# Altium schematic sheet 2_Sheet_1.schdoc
size 497 x 243 mm; Name: A_A4; Symbol: A_A4; Device: A_A4; @Project Name: RM_超级电容控制板; REV: 3.4; Date: 2023-02-08; Sheet: 1/3; Draw By: PKKKK; Company: QiDian; Convert to PCB: yes; Add into BOM: yes
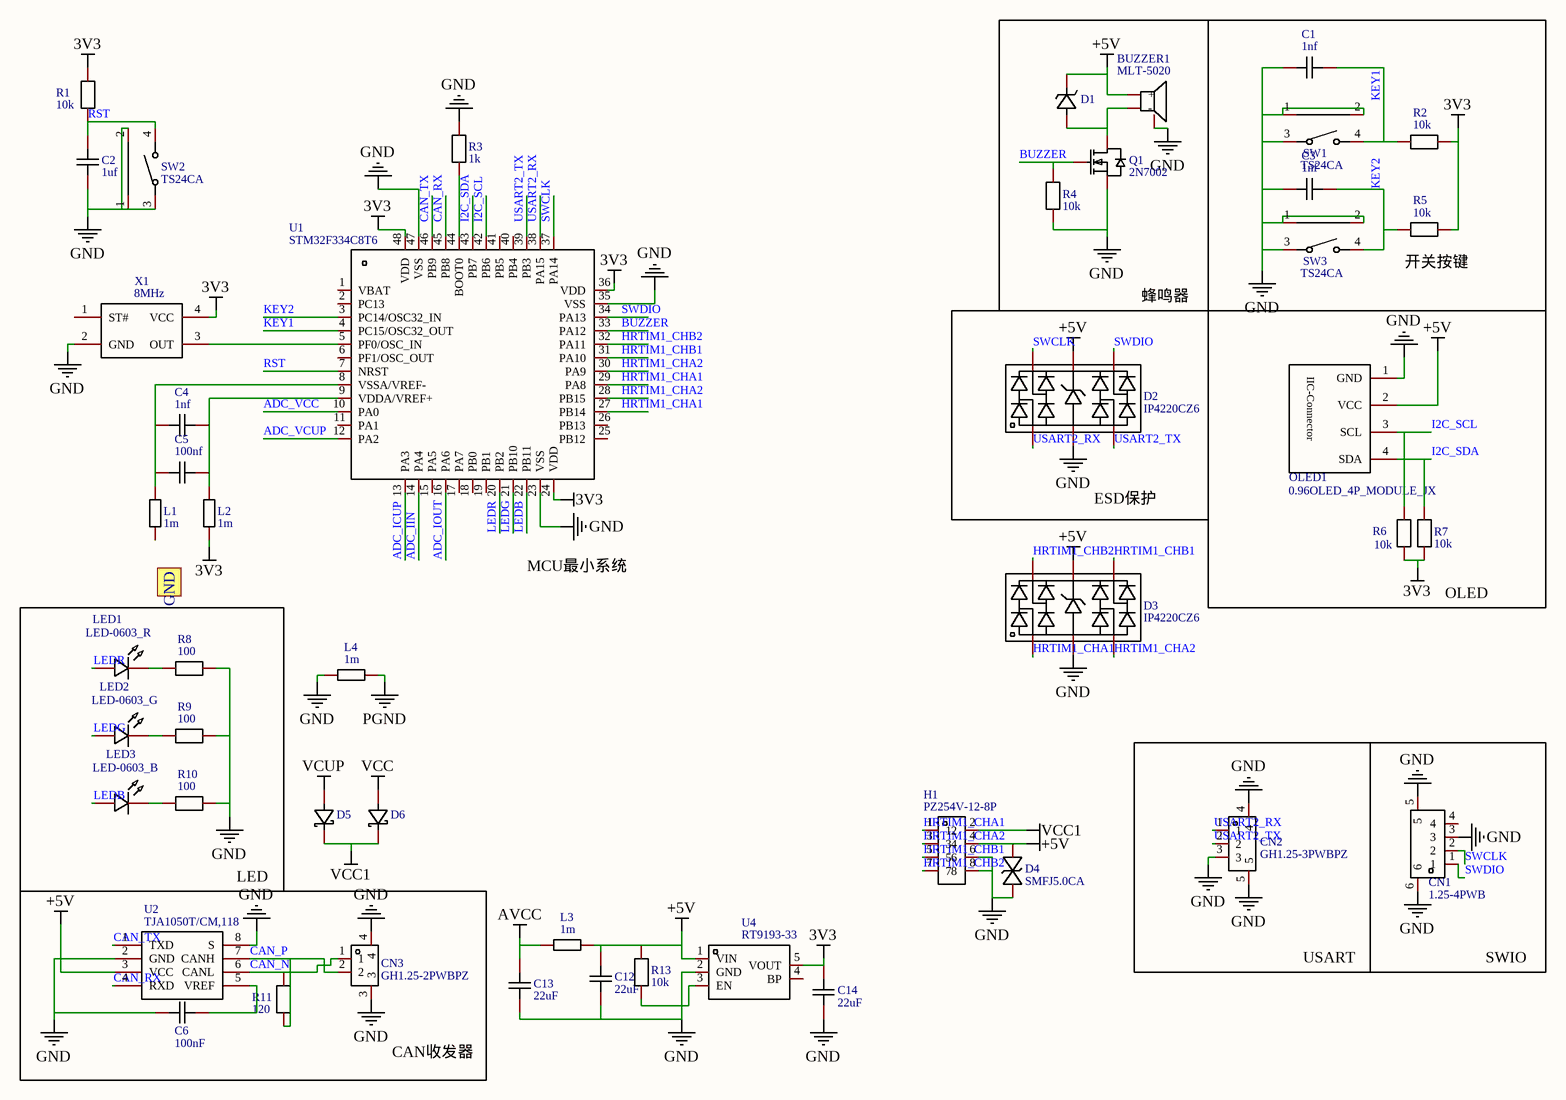
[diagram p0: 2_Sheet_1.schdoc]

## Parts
BUZZER1  MLT-5020  [BUZ-SMD_3P-L5.2-W5.2-P3.50-BR]
C1  1nf  [C0603]
C2  1uf  [C0603]
C3  1nf  [C0603]
C4  1nf  [C0603]
C5  100nf  [C0603]
C6  100nF  [C0603]
C12  22uF  [C0805]
C13  22uF  [C0805]
C14  22uF  [C0805]
CN1  1.25-4PWB  [CONN-SMD_1.25-4PWB]
CN2  GH1.25-3PWBPZ  [CONN-SMD_GH1.25-3PWBPZ]
CN3  GH1.25-2PWBPZ  [CONN-SMD_GH1.25-2PWBPZ]
D1  贴片二极管/JSPI3100A/SOD-123FL[捷捷微]  [SOD-123F_L2.7-W1.6-LS3.8-RD]  (value not drawn)
D2  IP4220CZ6  [SOT-23-6_L2.9-W1.6-P0.95-LS2.7-BL]
D3  IP4220CZ6  [SOT-23-6_L2.9-W1.6-P0.95-LS2.7-BL]
D4  SMFJ5.0CA  [SOD-123_L2.8-W1.8-LS3.7-BI]
D5  DSK310_C713648  [SOD-123_L2.7-W1.8-LS3.7-RD]  (value not drawn)
D6  DSK310_C713648  [SOD-123_L2.7-W1.8-LS3.7-RD]  (value not drawn)
H1  PZ254V-12-8P  [HDR-TH_8P-P2.54-V-M-R2-C4-S2.54]
L1  1m  [L0603]
L2  1m  [L0603]
L3  1m  [L0603]
L4  1m  [L0603]
LED1  LED-0603_R  [LED0603_RED]
LED2  LED-0603_G  [LED0603_RED]
LED3  LED-0603_B  [LED0603_RED]
OLED1  0.96OLED_4P_MODULE_JX  [排针2.54单排4PIN]
Q1  2N7002  [SOT-23_L2.9-W1.3-P0.95-LS2.4-BR]
R1  10k  [R0603]
R2  10k  [R0603]
R3  1k  [R0603]
R4  10k  [R0603]
R5  10k  [R0603]
R6  10k  [R0603]
R7  10k  [R0603]
R8  100  [R0603]
R9  100  [R0603]
R10  100  [R0603]
R11  120  [R0603]
R13  10k  [R0603]
SW1  TS24CA  [SW-SMD_TS24CA]
SW2  TS24CA  [SW-SMD_TS24CA]
SW3  TS24CA  [SW-SMD_TS24CA]
U1  STM32F334C8T6  [LQFP-48_L7.0-W7.0-P0.50-LS9.0-BL]
U2  TJA1050T/CM,118  [SOIC-8_L5.0-W4.0-P1.27-LS6.0-BL]
U4  RT9193-33  [SOT-23-5_L2.9-W1.6-P0.95-LS2.8-BL]
X1  8MHz  [OSC-SMD_4P-L3.2-W2.5-BL]

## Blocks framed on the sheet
蜂鸣器: BUZZER1 D1 Q1 R4
开关按键: C1 C3 R2 R5 SW1 SW3
OLED: OLED1 R6 R7
LED: LED1-LED3 R8-R10
USART: CN2
SWIO: CN1
CAN收发器: C6 CN3 R11 U2

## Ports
GND (out)

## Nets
3V3: C14.1 L2.2 R1.1 R2.2 R5.2 R6.1 R7.1 U1.24(VDD) U1.36(VDD) U1.48(VDD) U4.5(VOUT) X1.4(VCC)
+5V: BUZZER1.2(+) C12.1 D1.1(K) D2.5 D3.5 D4.2 H1.4 L3.1 OLED1.2(VCC) R13.2 U2.3(VCC) U4.1(VIN)
AVCC: C13.1 L3.2
GND: BUZZER1.1(NC) C1.1 C2.1 C3.1 C6.1 C12.2 C13.2 C14.2 CN1.3 CN1.5 CN1.6 CN2.3 CN2.4 CN2.5 CN3.3 CN3.4 D2.2 D3.2 D4.1 H1.6 H1.8 L4.2 OLED1.1(GND) Q1.2(S) R3.2 R4.1 R8.2 R9.2 R10.2 SW1.1 SW1.2 SW1.3 SW2.1 SW2.2 SW2.3 SW3.1 SW3.2 SW3.3 U1.23(VSS) U1.35(VSS) U1.47(VSS) U2.2(GND) U2.8(S) U4.2(GND) X1.2(GND)
PGND: L4.1
VCC: D6.2(A)
VCC1: D5.1(K) D6.1(K) H1.2
VCUP: D5.2(A)
ADC_ICUP: U1.13(PA3)
ADC_IIN: U1.14(PA4)
ADC_IOUT: U1.16(PA6)
ADC_VCC: U1.10(PA0)
ADC_VCUP: U1.12(PA2)
BUZZER: Q1.1(G) R4.2 U1.33(PA12)
CAN_N: CN3.1 R11.2 U2.6(CANL)
CAN_P: CN3.2 R11.1 U2.7(CANH)
CAN_RX: U1.45(PB8) U2.4(RXD)
CAN_TX: U1.46(PB9) U2.1(TXD)
HRTIM1_CHA1: D3.1 H1.1 U1.27(PB14) U1.29(PA8)
HRTIM1_CHA2: D3.3 H1.3 U1.28(PB15) U1.30(PA9)
HRTIM1_CHB1: D3.4 H1.5 U1.31(PA10)
HRTIM1_CHB2: D3.6 H1.7 U1.32(PA11)
I2C_SCL: OLED1.3(SCL) R6.2 U1.42(PB6)
I2C_SDA: OLED1.4(SDA) R7.2 U1.43(PB7)
KEY1: C1.2 R2.1 SW1.4 U1.4(PC15/OSC32_OUT)
KEY2: C3.2 R5.1 SW3.4 U1.3(PC14/OSC32_IN)
LEDB: LED3.1 U1.22(PB11)
LEDG: LED2.1 U1.21(PB10)
LEDR: LED1.1 U1.20(PB2)
RST: C2.2 R1.2 SW2.4 U1.7(NRST)
SWCLK: CN1.2 D2.6 U1.37(PA14)
SWDIO: CN1.1 D2.4 U1.34(PA13)
USART2_RX: CN2.1 D2.1 U1.38(PA15)
USART2_TX: CN2.2 D2.3 U1.39(PB3)
NetBUZZER1_3: BUZZER1.3(-) D1.2(A) Q1.3(D)
NetC4_1: C4.1 C5.1 L1.2 U1.8(VSSA/VREF-)
NetC4_2: C4.2 C5.2 L2.1 U1.9(VDDA/VREF+)
NetC6_2: C6.2 U2.5(VREF)
NetLED1_2: LED1.2 R8.1
NetLED2_2: LED2.2 R9.1
NetLED3_2: LED3.2 R10.1
NetR3_1: R3.1 U1.44(BOOT0)
NetR13_1: R13.1 U4.3(EN)
NetU1_5: U1.5(PF0/OSC_IN) X1.3(OUT)

Not connected (* = marked no-connect by the designer): CN1 4; L1 1; U1 1(VBAT) 2(PC13) 6(PF1/OSC_OUT) 11(PA1) 15(PA5) 17(PA7) 18(PB0) 19(PB1) 25(PB12) 26(PB13) 40(PB4) 41(PB5); U4 4(BP); X1 1(ST#)

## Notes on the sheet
- ESD保护
- MCU最小系统

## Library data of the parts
BUZZER1 = MLT-5020: Manufacturer: 华能; 3DModel: BUZ-SMD_3P-L5.2-W5.2-H2.0-P3.50; Frequency: 4000Hz; Add into BOM: yes
C1 C3 C4 = 1nf: 3DModel: C0603_L1.6-W0.8-H0.8; Add into BOM: yes
C2 = 1uf: 3DModel: C0603_L1.6-W0.8-H0.8; Add into BOM: yes
C5 C6 = 0.1uf: 3DModel: C0603_L1.6-W0.8-H0.8; Add into BOM: yes
C12-C14 = 22u: 3DModel: C0805_L2.0-W1.3-H1.3; Add into BOM: yes
CN1 = 1.25-4PWB: Manufacturer: DEALON(德艺隆); Add into BOM: yes
CN2 = GH1.25-3PWBPZ: Manufacturer: BOOMELE(博穆精密); Add into BOM: yes
CN3 = GH1.25-2PWBPZ: Manufacturer: BOOMELE(博穆精密); Add into BOM: yes
D1 = 贴片二极管/JSPI3100A/SOD-123FL[捷捷微]: Manufacturer: null; Add into BOM: yes
D2 D3 = IP4220CZ6: Manufacturer: UMW(友台半导体); Add into BOM: yes
D4 = SMFJ5.0CA: Manufacturer: BORN(伯恩半导体); Manufacturer Part: SMFJ3.3CA; 3DModel: SOD-123_L2.8-W1.8-H1.4-LS3.7; Add into BOM: yes
D5 D6 = DSK310_C713648: Manufacturer: LGE(鲁光); Manufacturer Part: DSK310; Add into BOM: yes
H1 = PZ254V-12-8P: Manufacturer: XFCN(兴飞); 3DModel: HDR-TH_8P-P2.54-M-LI-2X4P; Add into BOM: yes
L1-L4 = 1m: 3DModel: L0603_L1.6-W0.8-H0.5_BEAD; Add into BOM: yes
LED1 = LED-0603_R: Manufacturer: EVERLIGHT(台湾亿光); Manufacturer Part: 19-217/R6C-AL1M2VY/3T; Symbol: LED-0603_G; Add into BOM: yes
LED2 = LED-0603_G: Manufacturer: EVERLIGHT(台湾亿光); Manufacturer Part: 19-217/R6C-AL1M2VY/3T; Add into BOM: yes
LED3 = LED-0603_B: Manufacturer: EVERLIGHT(台湾亿光); Manufacturer Part: 19-217/R6C-AL1M2VY/3T; Symbol: LED-0603_G; Add into BOM: yes
OLED1 = 0.96OLED_4P_MODULE_JX: Manufacturer: null; 3DModel: OLED4P; Add into BOM: yes
Q1 = 2N7002: Manufacturer: Nexperia; Manufacturer Part: 2N7002,215; 3DModel: SOT-23-3P_L2.9-W1.3-H1.0-LS2.4-P0.95; Paste Type: expand; Add into BOM: yes
R1 R2 R4-R7 R13 = 10k: Add into BOM: yes
R3 = 1k: Add into BOM: yes
R8-R10 = 100: Add into BOM: yes
R11 = 120: Add into BOM: yes
SW1-SW3 = TS24CA: Manufacturer: SHOU HAN(首韩); Add into BOM: yes
U1 = STM32F334C8T6: Manufacturer: STMicroelectronics; 3DModel: LQFP-48_L7.0-W7.0-H1.4-LS9.0-P0.50; Add into BOM: yes
U2 = TJA1050T/CM,118: Manufacturer: NXP(恩智浦); 3DModel: SOIC-8_L4.9-W3.9-H1.7-LS6.0-P1.27; Add into BOM: yes
U4 = RT9193-33: Manufacturer: null; Add into BOM: yes
X1 = 8MHz: Manufacturer: EPSON; Manufacturer Part: Q33310F70055100; 3DModel: OSC-SMD_4P-L3.2-W2.5-H1.0; Add into BOM: yes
